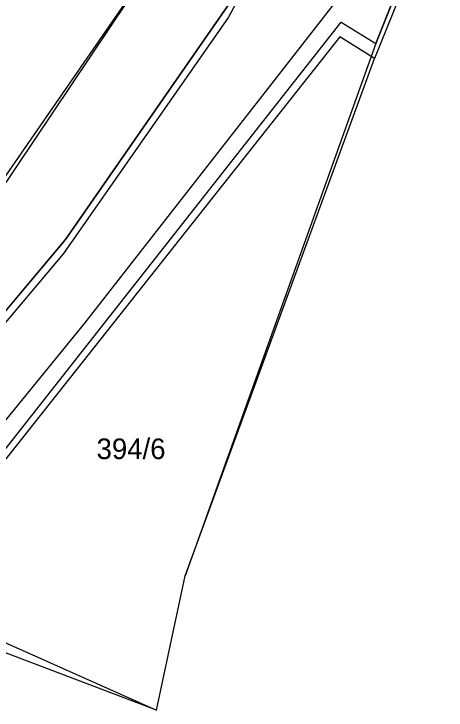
# Model space of a CAD drawing. Extents: x -678683 to -677755, y -1006946 to -1005971.
# Drawn here: x -678264.3 to -678222.4, y -1006518.1 to -1006450.6 of the extents above; entities that cross this region are included whole.
import ezdxf

# ---------------------------------------------------------------- set-up
doc = ezdxf.new("R2010")
doc.units = 0
for name, color, linetype in [('I_2_4_předběžný_vykres - SŽDC', 7, 'Continuous'), ('koor - SSZT_nové', 7, 'Continuous'), ('MapaKN - Mladejov+Strelec_dosavani+nova_situace - Vrstva 1', 7, 'Continuous'), ('MapaKN - Mladejov+Strelec_dosavani+nova_situace - Vrstva 11', 7, 'Continuous'), ('MapaKN - Mladejov+Strelec_dosavani+nova_situace - Vrstva 18', 7, 'Continuous'), ('MapaKN - původní vrstava 1', 7, 'Continuous')]:
    doc.layers.add(name, color=color, linetype=linetype)

msp = doc.modelspace()

# ---------------------------------------------------------------- linework, layer by layer
at = {"layer": 'I_2_4_předběžný_vykres - SŽDC'}
for p, q in [((-678229.19, -1006453.42), (-678223.89, -1006440.18)), ((-678243.35, -1006449.47), (-678259.32, -1006472.44)), ((-678265.21, -1006492.84), (-678232.55, -1006451.35)), ((-678232.55, -1006451.35), (-678229.19, -1006453.42)), ((-678259.32, -1006472.44), (-678273.34, -1006489.17))]:
    msp.add_line(p, q, dxfattribs=at)
at = {"layer": 'koor - SSZT_nové'}
msp.add_lwpolyline([(-678276.518, -1006503.932), (-678257.417, -1006480.575), (-678238.833, -1006456.747), (-678223.794, -1006437.464), (-678213.311, -1006424.022), (-678199.433, -1006408.271)], dxfattribs=at)
at = {"layer": 'MapaKN - Mladejov+Strelec_dosavani+nova_situace - Vrstva 1'}
msp.add_lwpolyline([(-678250.47, -1006518.1), (-678247.7, -1006505.06)], dxfattribs=at)
at = {"layer": 'MapaKN - Mladejov+Strelec_dosavani+nova_situace - Vrstva 11'}
for points in [[(-678223.89, -1006440.18), (-678229.19, -1006453.42)], [(-678272.96, -1006477.58), (-678249.68, -1006443.91)], [(-678259.32, -1006472.44), (-678243.35, -1006449.47)], [(-678265.21, -1006492.84), (-678232.55, -1006451.35)], [(-678232.55, -1006451.35), (-678229.19, -1006453.42)], [(-678229.19, -1006453.42), (-678247.7, -1006505.06)], [(-678273.34, -1006489.17), (-678259.32, -1006472.44)], [(-678272.25, -1006508.4), (-678250.47, -1006518.1)]]:
    msp.add_lwpolyline(points, dxfattribs=at)
at = {"layer": 'MapaKN - původní vrstava 1'}
for points in [[(-678223.98, -1006441.66), (-678229.32, -1006454.88)], [(-678273.17, -1006478.9), (-678249.68, -1006443.91)], [(-678242.05, -1006448.18), (-678243.47, -1006450.89)], [(-678243.47, -1006450.89), (-678259.51, -1006473.8)], [(-678232.67, -1006452.8), (-678265.47, -1006494.18)], [(-678229.32, -1006454.88), (-678232.67, -1006452.8)], [(-678247.7, -1006505.06), (-678229.32, -1006454.88)], [(-678259.51, -1006473.8), (-678273.59, -1006490.49)], [(-678250.47, -1006518.1), (-678272.56, -1006509.72)]]:
    msp.add_lwpolyline(points, dxfattribs=at)

# ---------------------------------------------------------------- texts
at = {"layer": 'MapaKN - Mladejov+Strelec_dosavani+nova_situace - Vrstva 18'}
msp.add_text('394/6', height=2, dxfattribs=at).set_placement((-678256.29, -1006493.75))

doc.saveas('drawing.dxf')
